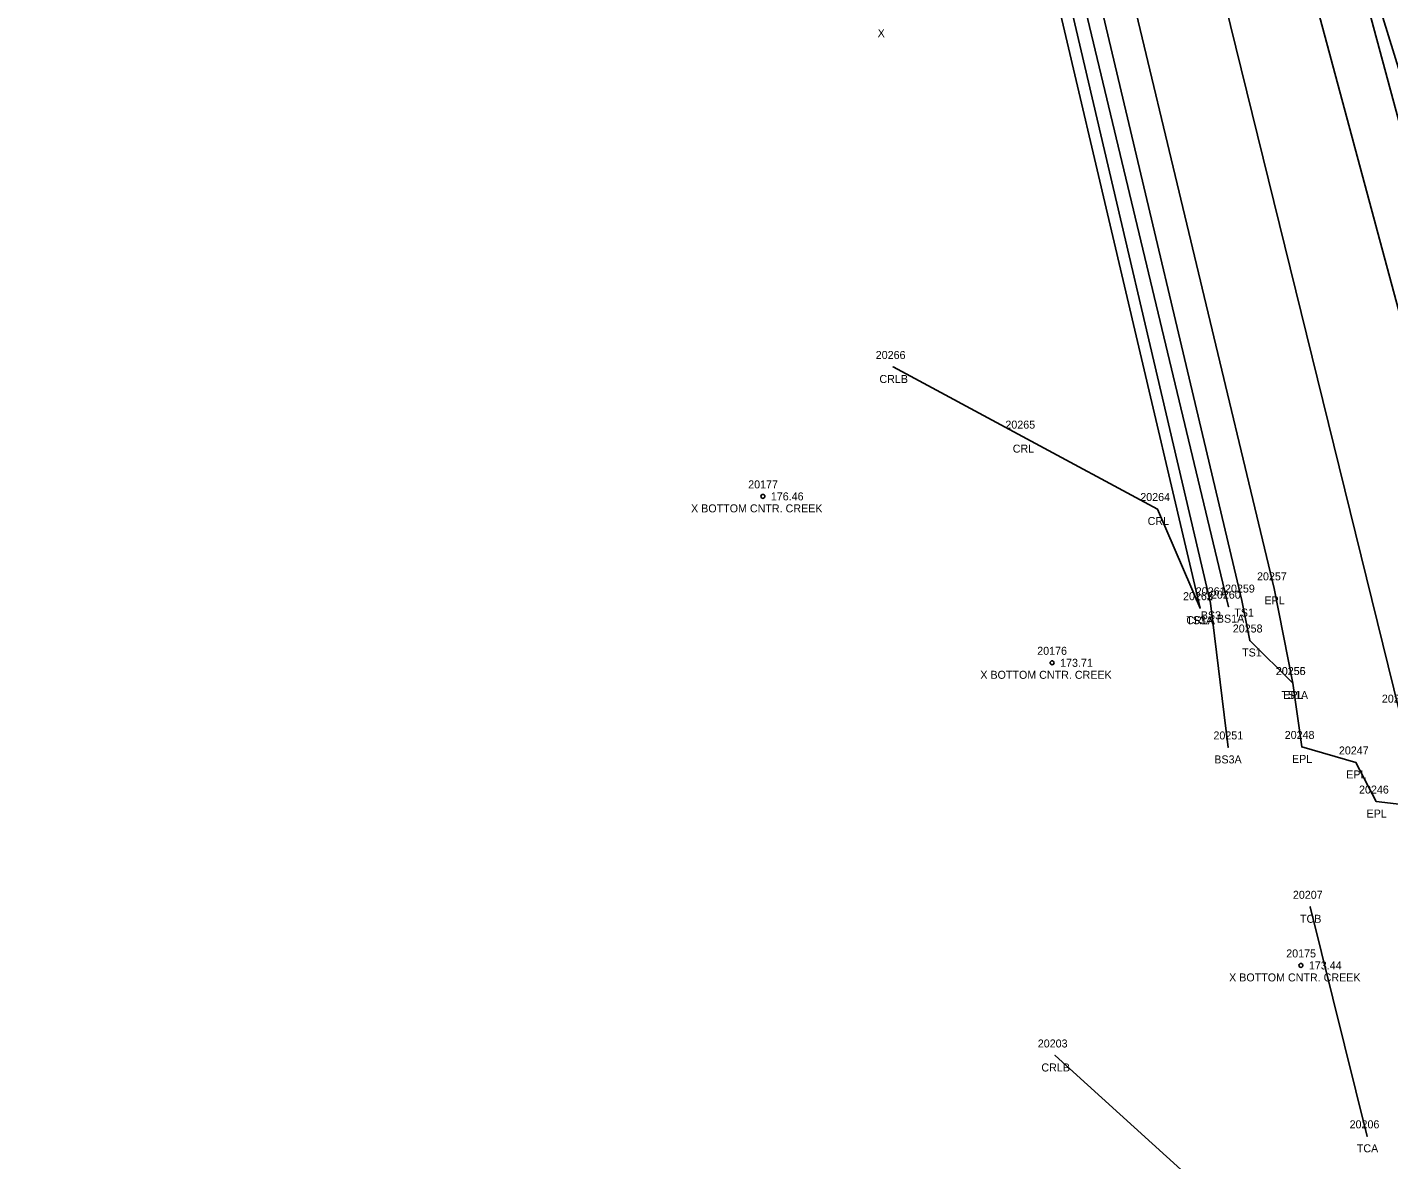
# Model space of a CAD drawing. Extents: x 2077883 to 2078272, y 787819 to 788945.
# Drawn here: x 2077915.3 to 2078085.4, y 788381 to 788522.7 of the extents above; entities that cross this region are included whole.
import ezdxf

# ---------------------------------------------------------------- set-up
doc = ezdxf.new("R2010")
doc.units = 0
for name, color, linetype in [('Default', 7, 'Continuous'), ('RD_DTM_BkLn1', 7, 'Continuous'), ('RD_DTM_BkLn2', 7, 'Continuous'), ('RD_EX_H2O', 7, 'Continuous'), ('RD_EX_H2O_txCode', 7, 'Continuous'), ('RD_EX_Road', 7, 'Continuous'), ('RD_EX_Road_txCode', 7, 'Continuous'), ('RD_Sketch8', 7, 'Continuous'), ('RD_SMD_Locator', 7, 'Continuous'), ('RD_SMD_Misc', 7, 'Continuous')]:
    doc.layers.add(name, color=color, linetype=linetype)

msp = doc.modelspace()

# ---------------------------------------------------------------- linework, layer by layer
at = {"layer": 'Default'}
msp.add_line((2078082.7, 788383.98), (2078075.59, 788412.68), dxfattribs=at)
for centre in [(2078075.59, 788412.68), (2078082.7, 788383.98)]:
    msp.add_circle(centre, 0.001, dxfattribs=at)
at = {"layer": 'RD_DTM_BkLn1'}
msp.add_lwpolyline([(2078089.54, 788425.19), (2078086.71, 788437.21), (2078062.2, 788536.79), (2078033.97, 788636.37), (2078001.1, 788734.32), (2077964.77, 788830.93), (2077924.88, 788926.7)], dxfattribs=at)
at = {"layer": 'RD_DTM_BkLn2'}
for points in [[(2078133.54, 788471.13), (2078119.08, 788459.82), (2078109.91, 788458.97), (2078096.37, 788486), (2078083.98, 788526.2), (2078079.55, 788541.15), (2078062.23, 788600.27), (2078049.45, 788641.41), (2078015.58, 788739.83), (2077979.12, 788836.63), (2077939.6, 788933.24)], [(2078134.43, 788470.29), (2078120, 788457.99), (2078107.89, 788457.91), (2078093.72, 788484.84), (2078082.52, 788526.41), (2078077.77, 788540.75), (2078060.01, 788599.41), (2078046.63, 788640.05), (2078012.72, 788738.62), (2077977.66, 788835.93), (2077936.62, 788932.18)], [(2078073.43, 788440.66), (2078068.04, 788445.98), (2078067.07, 788450.97), (2078047.86, 788532.15), (2078020.2, 788632.44), (2078011.47, 788662.76), (2078009.13, 788663.05), (2078006.78, 788662.29), (2078006.29, 788660.13)], [(2078065.37, 788450.21), (2078045.88, 788531.66), (2078018.55, 788632.15), (2078009.27, 788661.89), (2078008.07, 788661.37)], [(2078065.33, 788432.61), (2078063.14, 788450.63), (2078044.34, 788530.97), (2078017.09, 788631.87), (2078008.07, 788661.37)], [(2078061.84, 788450.02), (2078042.92, 788530.6), (2078015.11, 788630.96), (2078006.29, 788660.13)]]:
    msp.add_lwpolyline(points, dxfattribs=at)
at = {"layer": 'RD_EX_H2O'}
for points in [[(2078061.84, 788450.02), (2078056.51, 788462.42), (2078039.64, 788471.47), (2078023.46, 788480.18)], [(2078081.49, 788359.41), (2078065.72, 788374.14), (2078043.71, 788394.09)]]:
    msp.add_lwpolyline(points, dxfattribs=at)
at = {"layer": 'RD_EX_Road'}
for points in [[(2078107.13, 788420.86), (2078105.11, 788427.29), (2078111.84, 788429.2), (2078117.69, 788434.7), (2078115.66, 788443.13), (2078106.49, 788447.64), (2078097.77, 788449.71), (2078094.97, 788456.34), (2078072.64, 788539.43), (2078043.77, 788639.22), (2078010.2, 788737.35), (2077974.01, 788834.54), (2077934.07, 788930.86)], [(2078107.13, 788420.86), (2078092.81, 788417.62), (2078089.54, 788425.19), (2078083.84, 788425.84), (2078081.3, 788430.73), (2078074.53, 788432.67), (2078073.43, 788440.66), (2078071.07, 788452.5), (2078051.67, 788533.56), (2078023.01, 788633.14), (2078012.91, 788665.11), (2078004.86, 788689.7), (2077990.53, 788730.26), (2077954.65, 788827.14), (2077915.26, 788922.36)]]:
    msp.add_lwpolyline(points, dxfattribs=at)
at = {"layer": 'RD_SMD_Locator'}
for centre, radius in [((2078023.46, 788480.18), 0.001), ((2078039.64, 788471.47), 0.001), ((2078007.19, 788464), 0.25), ((2078056.51, 788462.42), 0.001), ((2078071.07, 788452.5), 0.001), ((2078061.84, 788450.02), 0.001), ((2078061.84, 788450.02), 0.001), ((2078063.14, 788450.63), 0.001), ((2078065.37, 788450.21), 0.001), ((2078067.07, 788450.97), 0.001), ((2078068.04, 788445.98), 0.001), ((2078043.34, 788443.19), 0.25), ((2078073.43, 788440.66), 0.001), ((2078073.43, 788440.66), 0.001), ((2078065.33, 788432.61), 0.001), ((2078074.53, 788432.67), 0.001), ((2078081.3, 788430.73), 0.001), ((2078083.84, 788425.84), 0.001), ((2078074.43, 788405.35), 0.25), ((2078043.71, 788394.09), 0.001)]:
    msp.add_circle(centre, radius, dxfattribs=at)

# ---------------------------------------------------------------- texts
at = {"layer": 'RD_EX_H2O_txCode'}
for s, p in [('20266', (2078021.3, 788481.18)), ('CRLB', (2078021.76, 788478.18)), ('20265', (2078037.5, 788472.47)), ('CRL', (2078038.42, 788469.47)), ('20264', (2078054.36, 788463.42)), ('CRL', (2078055.28, 788460.42)), ('20263', (2078059.7, 788451.02)), ('CRLA', (2078060.12, 788448.02)), ('20203', (2078041.55, 788395.09)), ('CRLB', (2078042, 788392.09))]:
    msp.add_text(s, height=1, dxfattribs=at).set_placement(p)
at = {"layer": 'RD_EX_Road_txCode'}
for s, p in [('20257', (2078068.95, 788453.5)), ('EPL', (2078069.87, 788450.5)), ('20255', (2078071.31, 788441.66)), ('EPL', (2078072.23, 788438.66)), ('20248', (2078072.41, 788433.67)), ('EPL', (2078073.32, 788430.67)), ('20247', (2078079.18, 788431.73)), ('EPL', (2078080.09, 788428.73)), ('20246', (2078081.7, 788426.84)), ('EPL', (2078082.64, 788423.84))]:
    msp.add_text(s, height=1, dxfattribs=at).set_placement(p)
at = {"layer": 'RD_Sketch8'}
for s, p in [('X', (2078021.54, 788521.42)), ('20177', (2078005.36, 788465)), ('176.46', (2078008.19, 788463.5)), ('X BOTTOM CNTR. CREEK', (2077998.22, 788462)), ('20176', (2078041.48, 788444.19)), ('173.71', (2078044.34, 788442.69)), ('X BOTTOM CNTR. CREEK', (2078034.37, 788441.19)), ('20175', (2078072.6, 788406.35)), ('173.44', (2078075.43, 788404.85)), ('X BOTTOM CNTR. CREEK', (2078065.46, 788403.35))]:
    msp.add_text(s, height=1, dxfattribs=at).set_placement(p)
at = {"layer": 'RD_SMD_Misc'}
for s, p in [('20262', (2078059.7, 788451.02)), ('20261', (2078061.29, 788451.63)), ('20260', (2078063.19, 788451.21)), ('20259', (2078064.95, 788451.97)), ('TS1', (2078066.11, 788448.97)), ('TS3A', (2078060.11, 788448.02)), ('BS3', (2078061.92, 788448.63)), ('BS1A', (2078063.93, 788448.21)), ('20258', (2078065.92, 788446.98)), ('TS1', (2078067.08, 788443.98)), ('20256', (2078071.29, 788441.66)), ('TS1A', (2078071.98, 788438.66)), ('20250', (2078084.55, 788438.21)), ('20251', (2078063.5, 788433.61)), ('BS3A', (2078063.61, 788430.61)), ('20207', (2078073.43, 788413.68)), ('TCB', (2078074.32, 788410.68)), ('20206', (2078080.52, 788384.98)), ('TCA', (2078081.42, 788381.98))]:
    msp.add_text(s, height=1, dxfattribs=at).set_placement(p)

doc.saveas('drawing.dxf')
